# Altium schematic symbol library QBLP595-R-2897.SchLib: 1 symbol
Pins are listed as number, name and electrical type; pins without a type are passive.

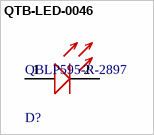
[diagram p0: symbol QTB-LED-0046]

## QTB-LED-0046
designator D?, comment QBLP595-R-2897
LED RED CLEAR 0402 SMD; Manufacturer: QT Brightek (QTB); Lens Size: 0.5mm; Dominant Wavelength: 620nm; Forward Voltage: 2.1V; Lens Color: Colorless; Luminous Intensity: 330mcd; Test Current: 20mA; Viewing Angle: 140°; Lens Style: Flat
footprint FP-QBLP595-R-2897-MFG
pins: 1 ANODE (+), 2 CATHODE (-)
